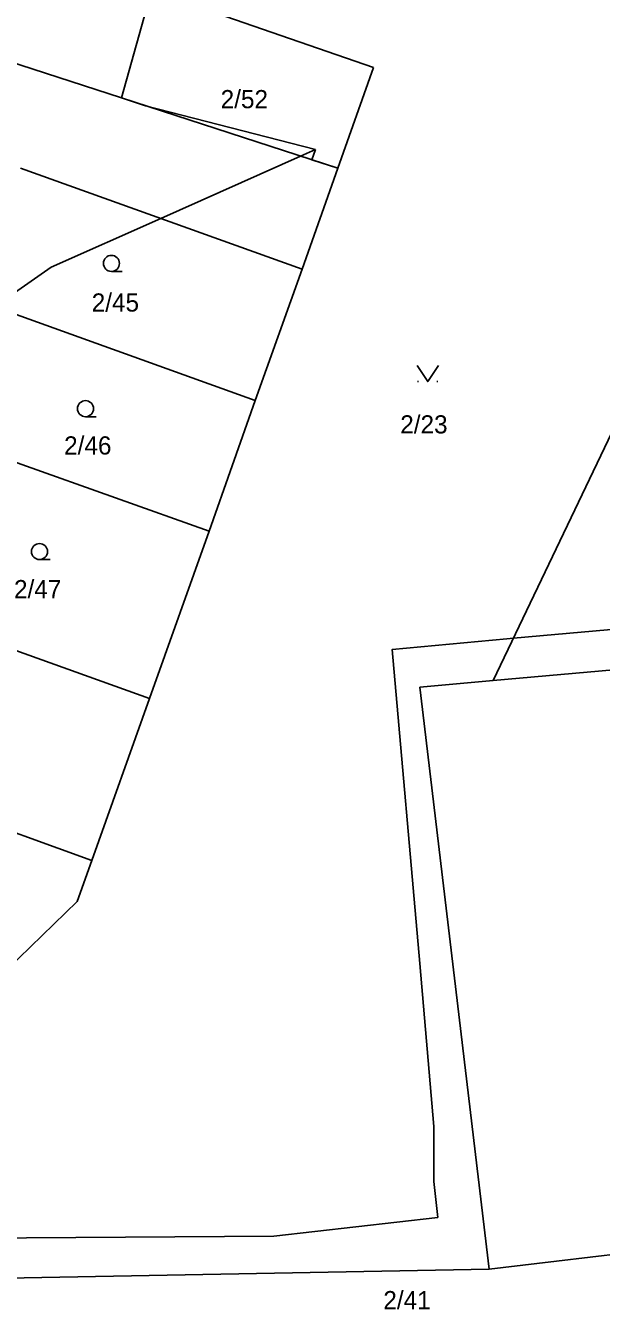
# Model space of a CAD drawing. Extents: x -747333 to -745433, y -1133152 to -1130600.
# Drawn here: x -746037.5 to -745983.7, y -1131642.6 to -1131522.4 of the extents above; entities that cross this region are included whole.
import ezdxf

# ---------------------------------------------------------------- set-up
doc = ezdxf.new("R2010")
doc.units = 0
for name, color, linetype in [('Vrstva 1', 7, 'Continuous'), ('Vrstva 18', 7, 'Continuous'), ('Vrstva 25', 7, 'Continuous'), ('Vrstva 52', 7, 'Continuous')]:
    doc.layers.add(name, color=color, linetype=linetype)

msp = doc.modelspace()

# ---------------------------------------------------------------- linework, layer by layer
at = {"layer": 'Vrstva 1'}
for points in [[(-746028.56, -1131529.17), (-746058.14, -1131519.53)], [(-746025.75, -1131519.12), (-746028.56, -1131529.17)], [(-746005.02, -1131526.33), (-746025.75, -1131519.12)], [(-746008.35, -1131535.75), (-746005.02, -1131526.33)], [(-746008.35, -1131535.75), (-746028.56, -1131529.17)], [(-746011.68, -1131545.17), (-746038, -1131535.74)], [(-746011.68, -1131545.17), (-746008.35, -1131535.75)], [(-745974.76, -1131543.78), (-745993.84, -1131583.67)], [(-746016.06, -1131557.46), (-746011.68, -1131545.17)], [(-746042.33, -1131548.02), (-746016.06, -1131557.46)], [(-746016.06, -1131557.46), (-746020.37, -1131569.7)], [(-746020.37, -1131569.7), (-746046.66, -1131560.32)], [(-746020.37, -1131569.7), (-746025.95, -1131585.34)], [(-745893.35, -1131574.74), (-745993.84, -1131583.67)], [(-746025.95, -1131585.34), (-746052.16, -1131575.92)], [(-745993.84, -1131583.67), (-746000.67, -1131584.28)], [(-746000.67, -1131584.28), (-745994.2, -1131638.7)], [(-746025.95, -1131585.34), (-746031.34, -1131600.5)], [(-746031.34, -1131600.5), (-746057.47, -1131591.02)], [(-746031.34, -1131600.5), (-746032.7, -1131604.32)], [(-746032.7, -1131604.32), (-746041.46, -1131612.82)], [(-745994.2, -1131638.7), (-745887.25, -1131625.98)], [(-745994.2, -1131638.7), (-746069.45, -1131640.11)]]:
    msp.add_lwpolyline(points, dxfattribs=at)
at = {"layer": 'Vrstva 25'}
for p, q in [((-746029.5, -1131545.39), (-746028.5, -1131545.39)), ((-746000.89, -1131555.69), (-746000.79, -1131555.69)), ((-745999.09, -1131555.69), (-745998.99, -1131555.69)), ((-746031.92, -1131558.98), (-746030.92, -1131558.98)), ((-746036.22, -1131572.35), (-746035.22, -1131572.35))]:
    msp.add_line(p, q, dxfattribs=at)
msp.add_lwpolyline([(-746000.94, -1131554.19), (-745999.94, -1131555.69), (-745998.94, -1131554.19)], dxfattribs=at)
for centre in [(-746029.5, -1131544.64), (-746031.92, -1131558.23), (-746036.22, -1131571.6)]:
    msp.add_circle(centre, 0.75, dxfattribs=at)
at = {"layer": 'Vrstva 52'}
for points in [[(-746010.44, -1131534), (-746026.3, -1131529.91), (-746028.56, -1131529.17), (-746025.75, -1131519.12), (-746016.9, -1131498.7), (-745989.55, -1131489.64), (-745987.12, -1131479.66), (-745954.58, -1131488.31), (-745953.84, -1131486.8), (-745949.25, -1131488), (-745940.31, -1131468.87), (-745927.94, -1131443.38)], [(-746010.44, -1131534), (-746011.83, -1131534.62), (-746024.89, -1131540.44), (-746035.13, -1131545), (-746040.47, -1131548.69), (-746043.24, -1131550.6), (-746053.66, -1131557.8), (-746059.79, -1131562.03), (-746070.44, -1131569.39), (-746075.13, -1131572.63), (-746084.55, -1131581.34), (-746090.81, -1131587.12), (-746096.74, -1131592.89), (-746101.45, -1131597.47), (-746104.44, -1131600.38), (-746122, -1131624.81), (-746123.64, -1131627.09), (-746128.25, -1131633.5), (-746131.25, -1131636), (-746131.39, -1131636.2), (-746141.16, -1131649.89)], [(-746053.5, -1131624.53), (-746041.46, -1131612.82), (-746032.7, -1131604.32), (-746031.34, -1131600.5), (-746025.95, -1131585.34), (-746020.37, -1131569.7), (-746016.06, -1131557.46), (-746011.68, -1131545.17), (-746008.35, -1131535.75), (-746010.77, -1131534.96), (-746010.44, -1131534)], [(-745893.94, -1131571), (-745991.94, -1131579.69), (-745992.56, -1131579.75), (-746003.25, -1131580.75), (-746000.69, -1131610.12), (-745999.38, -1131625.38), (-745999.38, -1131630.5), (-745999, -1131633.88), (-746014.31, -1131635.62), (-746065.23, -1131635.98), (-746053.5, -1131624.53)]]:
    msp.add_lwpolyline(points, dxfattribs=at)

# ---------------------------------------------------------------- texts
at = {"layer": 'Vrstva 18'}
for s, p in [('2/52', (-746019.29, -1131530.13)), ('2/45', (-746031.34, -1131549.15)), ('2/23', (-746002.51, -1131560.55)), ('2/46', (-746033.92, -1131562.52)), ('2/47', (-746038.6, -1131575.96)), ('2/41', (-746004.09, -1131642.46))]:
    msp.add_text(s, height=1.7, dxfattribs=at).set_placement(p)

doc.saveas('drawing.dxf')
